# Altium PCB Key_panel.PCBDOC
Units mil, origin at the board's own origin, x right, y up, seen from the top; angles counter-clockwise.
Board outline 6000 x 4000 mil, 2 copper layers (Top Layer, Bottom Layer); 13 components, 10 nets, 42 pads, 0 vias.
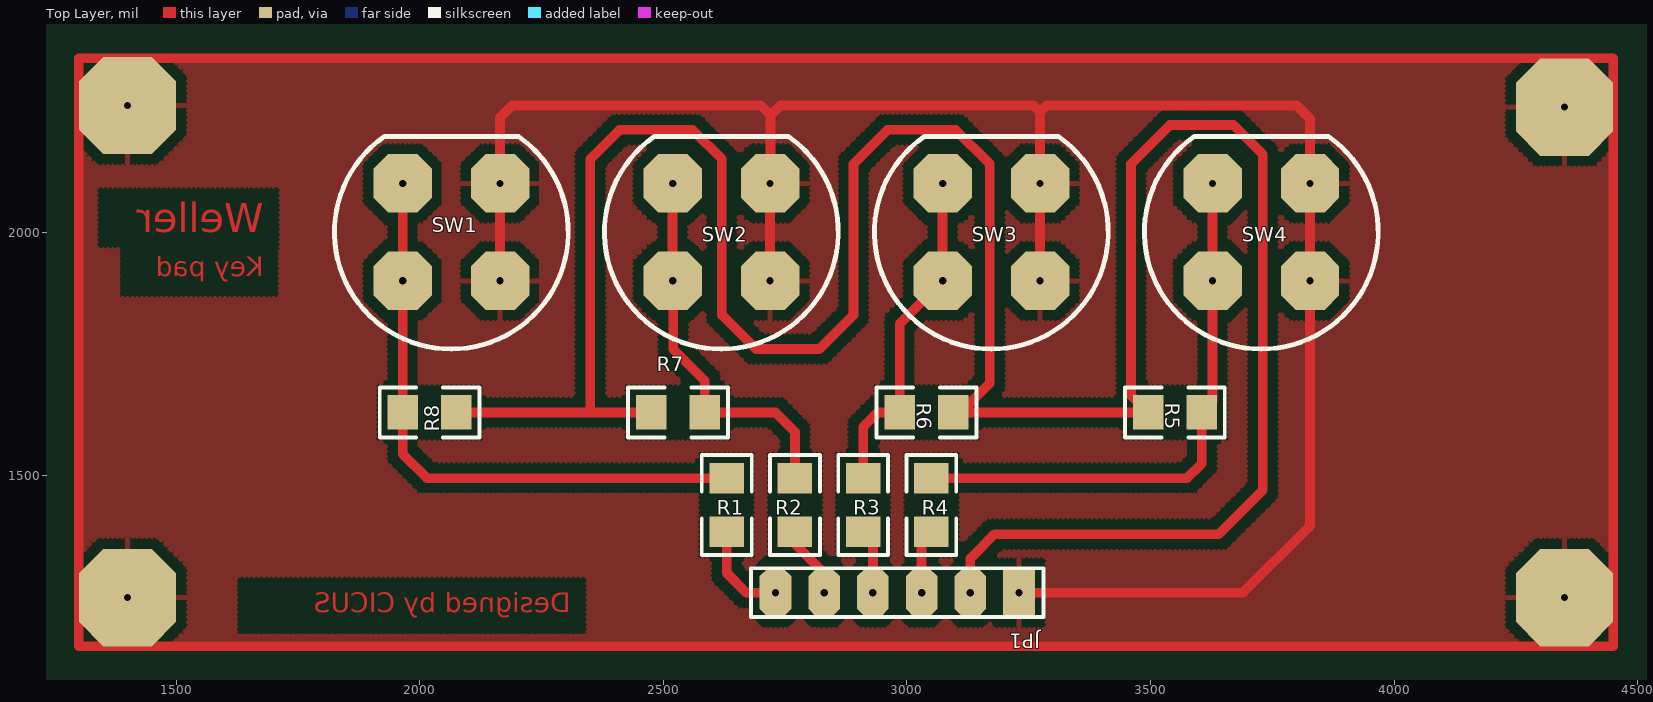
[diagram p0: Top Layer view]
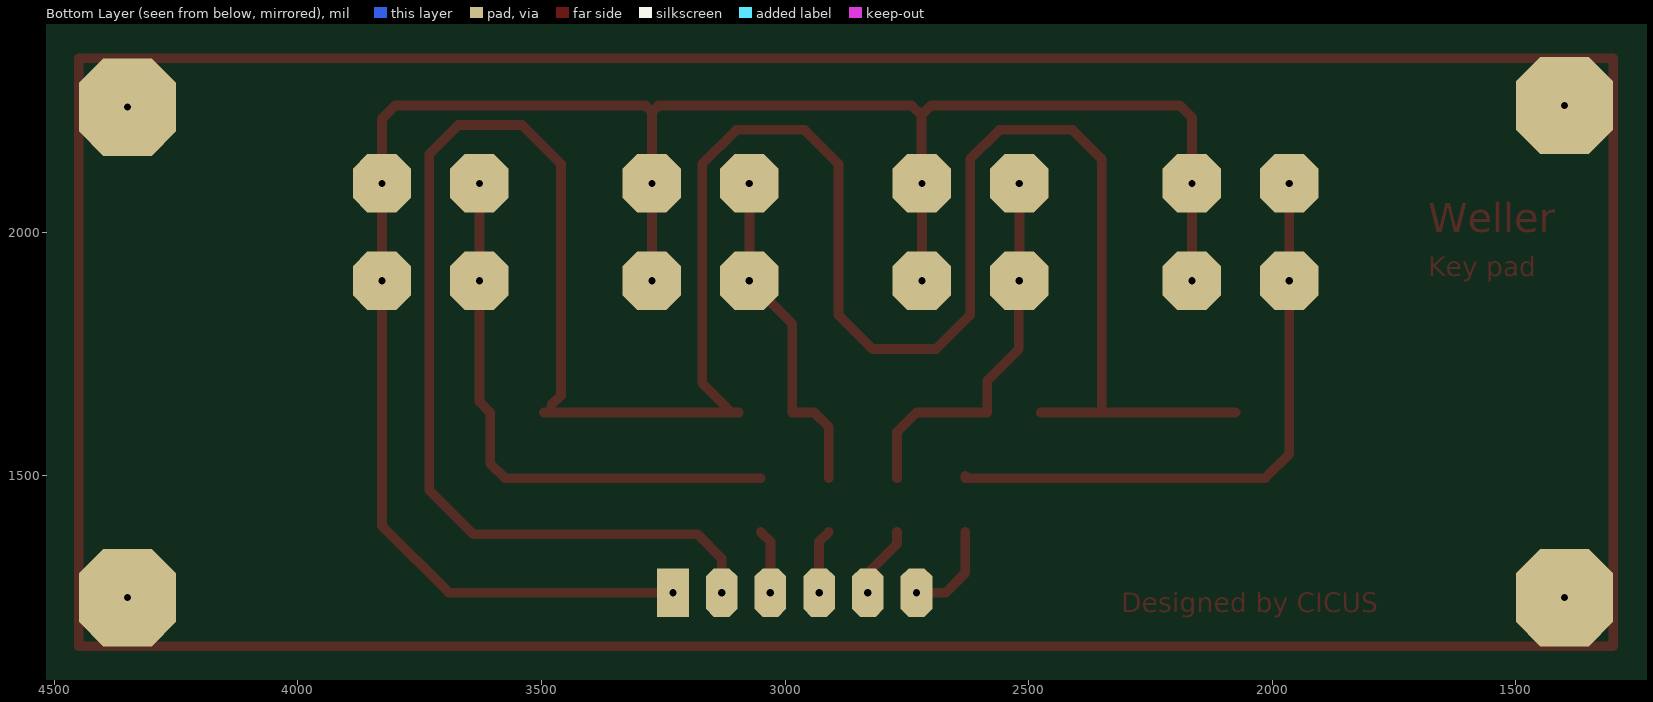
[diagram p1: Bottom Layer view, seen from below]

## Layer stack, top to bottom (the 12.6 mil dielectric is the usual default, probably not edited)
Top Layer: signal copper 1.4
Dielectric: dielectric 12.6, FR-4, Dk 4.8
Bottom Layer: signal copper 1.4

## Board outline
1000,1000 1000,5000 7000,5000 7000,1000

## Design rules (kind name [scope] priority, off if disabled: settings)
Clearance [All] p1: gap=20
ComponentClearance [All] p1: gap=10 collisioncheckmode=0
PolygonConnect [All] p1: connectstyle=Relief reliefconductorwidth=10 reliefentries=4 polygonreliefangle="90 Angle"
RoutingLayers [All] p1: top layer=Horizontal bottom layer=Vertical
RoutingVias [All] p1: holewidth=28 width=50 viastyle="Through Hole" minholewidth=28 minwidth=50 maxholewidth=28 maxwidth=50
SolderMaskExpansion [All] p1: expansion=4
TestPointUsage [All] p1: valid=0 allowmultiple=FALSE
Testpoint [All] p1: side=15 testpointundercomponent=TRUE minsize=40 maxsize=100 preferedsize=60 minholesize=0 maxholesize=40 preferedholesize=32 testpointgrid=1 style=1023 order=1234567890
Width [All] p1: maxlimit=50 minlimit=10 preferedwidth=20
10 further rules are at their usual default settings.

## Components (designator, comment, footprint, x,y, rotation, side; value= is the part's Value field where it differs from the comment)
JP1 "Header 6" HDR1X6 3230,1260 r180 top
R1 "Res2" C3216-1206 2630,1440 r90 top
R2 "Res2" C3216-1206 2770,1440 r90 top
R3 "Res2" C3216-1206 2910,1440 r90 top
R4 "Res2" C3216-1206 3050,1440 r90 top
R5 "Res2" C3216-1206 3550,1630 r0 top
R6 "Res2" C3216-1206 3040,1630 r180 top
R7 "Res2" C3216-1206 2530,1630 r0 top
R8 "Res2" C3216-1206 2020,1630 r180 top
SW1 "Push Button" PushButton 1964.76,2100 r0 top
SW2 "Push Button" PushButton 2518.92,2100 r0 top
SW3 "Push Button" PushButton 3073.07,2100 r0 top
SW4 "Push Button" PushButton 3627.22,2100 r0 top

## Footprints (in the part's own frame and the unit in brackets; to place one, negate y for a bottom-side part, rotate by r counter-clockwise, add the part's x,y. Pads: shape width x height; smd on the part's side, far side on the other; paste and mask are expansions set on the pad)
C3216-1206 [mm]
  rect 1.6x1.8 smd: 1(-1.4,0) 2(1.4,0)
  silkscreen extent -2.6,-1.3 2.6,1.3
HDR1X6 [mil]
  rect 65x100 hole 15: 1(0,0)
  oct 65x100 hole 15: 2(100,0) 3(200,0) 4(300,0) 5(400,0) 6(500,0)
  silkscreen extent -50,-50 550,50
PushButton [mil]
  oct 120x120 hole 15: 1(0,0) 2(0,-200) 3(200,-200) 4(200,0)
  silkscreen extent -140,-340 340,97

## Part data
JP1: "Header, 6-Pin"
R1 R2 R3 R4 R5 R6 R7 R8: "Resistor"
SW1 SW2 SW3 SW4: library part PUSHBUTTON

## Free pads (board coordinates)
  oct 200x200 hole 15: 0(1400,2260) 1(4349.6,2256.8) 2(4349.6,1250) 3(1400,1250)

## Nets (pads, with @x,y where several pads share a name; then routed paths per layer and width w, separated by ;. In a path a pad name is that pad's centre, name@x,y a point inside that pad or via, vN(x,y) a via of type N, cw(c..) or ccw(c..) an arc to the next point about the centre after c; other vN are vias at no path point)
NetJP1_1: JP1.1 pad.0 pad.1 pad.2 pad.3 SW1.3 SW1.4 SW2.3 SW2.4 SW3.3 SW3.4 SW4.3 SW4.4 | length 12936
  Top Layer w20: SW1.3 2164.76,2235.24 2189.52,2260 2700,2260 2720,2240 ; SW2.3 SW2.4 ; SW2.4@2720,2100 2720,2240 ; JP1.1 3690,1260 3827.22,1397.22 3827.22,2232.78 3800,2260 3286.14,2260 3273.07,2246.93 ; SW3.3 3273.07,2246.93 ; 2720,2240 2740,2260 3260,2260 3273.07,2246.93 ; 1300,1150 1300,2356.8 4449.6,2356.8 4449.6,1150 1300,1150
NetJP1_2: JP1.2 R5.1 R6.1 R7.1 R8.1 | length 5719.4
  Top Layer w20: R8.1 R7.1 ; 2350,1630 2350,2150 2410,2210 2560,2210 2620,2150 2620,1830 2690,1760 2820,1760 2890,1830 2890,2140 2960,2210 3100,2210 3170,2140 3170,1690 R6.1@3110,1630 ; R6.1 R5.1 ; JP1.2 3130,1330 3180,1380 3640,1380 3730,1470 3730,2160 3670,2220 3540,2220 3460,2140 3460,1664.88 R5.1@3480,1644.88
NetJP1_3: JP1.3 R4.1 | length 133.2
  Top Layer w20: JP1.3 3030,1364.88 R4.1
NetJP1_4: JP1.4 R3.1 | length 133.2
  Top Layer w20: R3.1 2930,1364.88 JP1.4
NetJP1_5: JP1.5 R2.1 | length 149.7
  Top Layer w20: R2.1 2770,1360 2830,1300 JP1.5
NetJP1_6: JP1.6 R1.1 | length 201.5
  Top Layer w20: R1.1 2630,1300 2670,1260 JP1.6
NetR1_2: R1.2 R8.2 SW1.1 SW1.2 | length 1245.6
  Top Layer w20: SW1.1 SW1.2 1964.88,1899.88 1964.88,1545.12 2014.88,1495.12 R1.2 R1.2@2630,1500
NetR2_2: R2.2 R7.2 SW2.1 SW2.2 | length 793.8
  Top Layer w20: SW2.1 SW2.2 2520,1898.92 2520,1760 2585.12,1694.88 R7.2 2730,1630 2770,1590 R2.2
NetR3_2: R3.2 R6.2 SW3.1 SW3.2 | length 708.5
  Top Layer w20: R3.2 2910,1600 2940,1630 R6.2 2984.88,1811.81 SW3.2 ; SW3.1 SW3.2 ; SW3.2@3080,1893.07 SW3.2
NetR4_2: R4.2 R5.2 SW4.1 SW4.2 | length 1161.8
  Top Layer w20: R4.2 3575.12,1495.12 3605.12,1525.12 R5.2 3627.22,1652.1 SW4.1 ; SW4.2@3620,1892.78 SW4.2

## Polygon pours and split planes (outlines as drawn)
NetJP1_1 on Top Layer (hatched 90Degree grid 0 track 10): 1300,2356.8 4449.6,2356.8 4449.6,1150 1300,1150

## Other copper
Top Layer:
  text "Weller" at 1680,2000 h60
  text "Key pad" at 1680,1910 h40
  text "Designed by CICUS" at 2310,1220 h40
